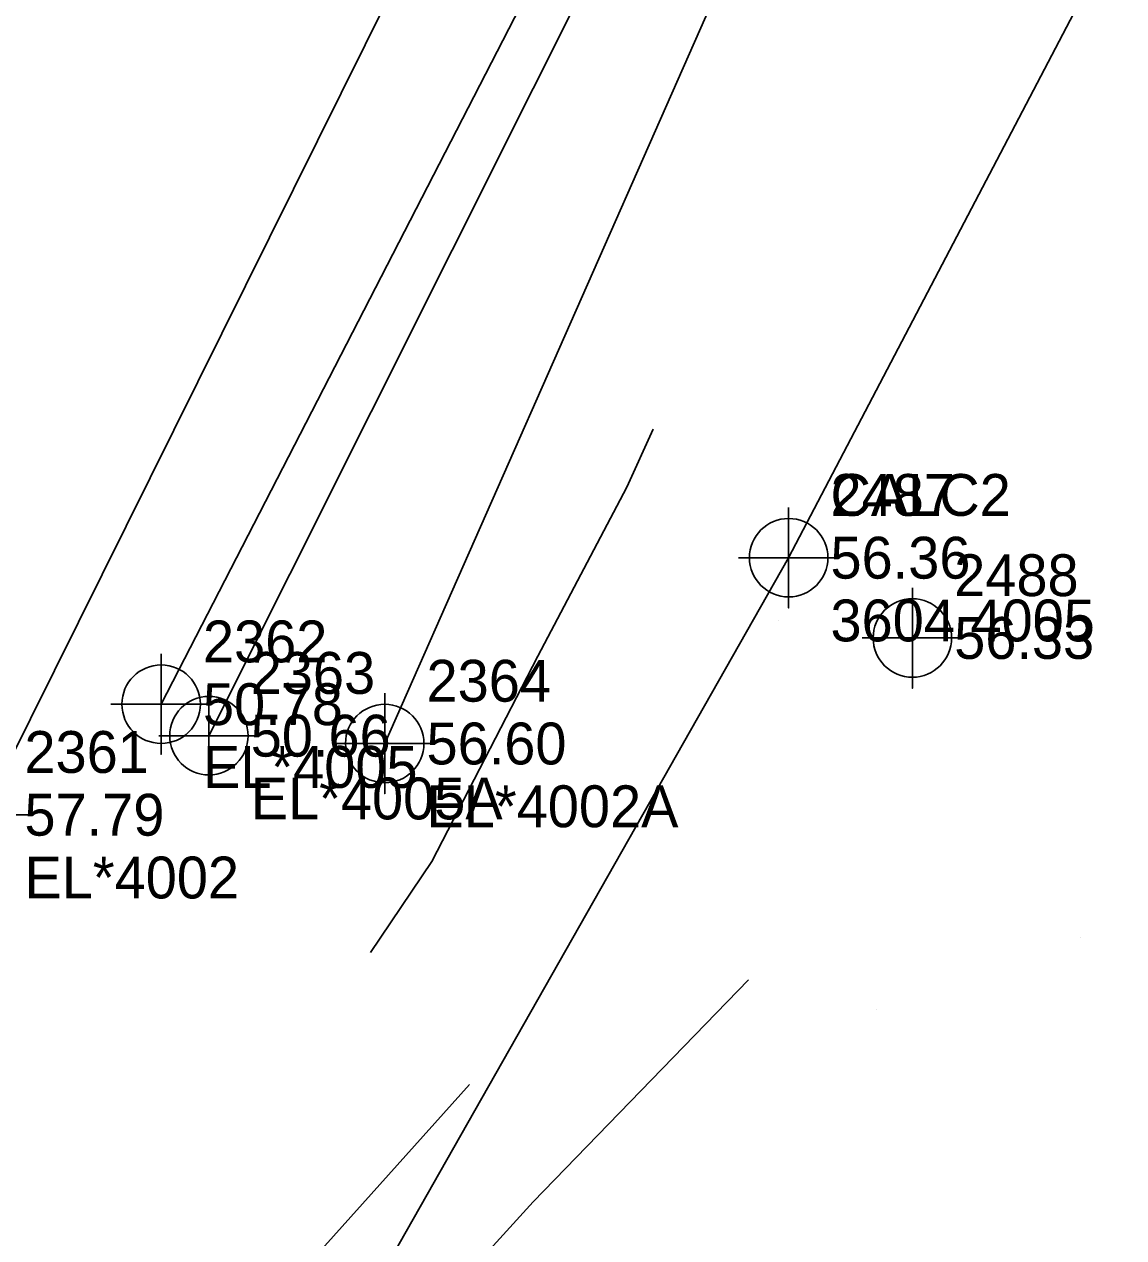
# Model space of a CAD drawing. Extents: x 2062781 to 2066835, y 358981 to 366501.
# Drawn here: x 2065856.5 to 2065922.3, y 364830.6 to 364903.1 of the extents above; entities that cross this region are included whole.
import ezdxf

# ---------------------------------------------------------------- set-up
doc = ezdxf.new("R2010")
doc.units = 0
for name, color, linetype in [('Exist DTM Breakline', 7, 'Continuous'), ('Exist DTM Breakline Cogo Comment', 7, 'Continuous'), ('Exist DTM Breakline Cogo Elevation', 7, 'Continuous'), ('Exist DTM Breakline Cogo Number', 7, 'Continuous'), ('Exist DTM Breakline Cogo Point CELL', 7, 'Continuous'), ('Exist DTM Regular Point CELL', 7, 'Continuous'), ('Exist DTM Regular Point Cogo Elevation', 7, 'Continuous'), ('Exist DTM Regular Point Cogo Number', 7, 'Continuous'), ('Exist DTM Ridgeline', 7, 'Continuous'), ('Exist DTM Ridgeline Cogo Comment', 7, 'Continuous'), ('Exist DTM Ridgeline Cogo Elevation', 7, 'Continuous'), ('Exist DTM Ridgeline Cogo Number', 7, 'Continuous'), ('Exist DTM Ridgeline Cogo Point CELL', 7, 'Continuous'), ('Exist Vegetation Woods Line Cogo Comment', 7, 'Continuous'), ('Exist Vegetation Woods Line Cogo Elevation', 7, 'Continuous'), ('Exist Vegetation Woods Line Cogo Number', 7, 'Continuous'), ('Exist Vegetation Woods Line Cogo Point CELL', 7, 'Continuous'), ('PH Exist DTM Breakline', 7, 'Continuous'), ('PH Exist DTM Point', 7, 'Continuous')]:
    doc.layers.add(name, color=color, linetype=linetype)

msp = doc.modelspace()

# ---------------------------------------------------------------- linework, layer by layer
at = {"layer": 'Exist DTM Breakline'}
for points in [[(2066156.831, 365415.162), (2066147.019, 365417.178), (2066143.489, 365410.654), (2066124.678, 365374.26), (2066094.453, 365314.73), (2066075.651, 365276.959), (2066045.171, 365217.477), (2066024.762, 365178.909), (2065998.134, 365126.307), (2065983.135, 365093.29), (2065946.309, 365022.693), (2065928.627, 364987.732), (2065911.277, 364951.078), (2065894.864, 364921.035), (2065864.729, 364862.524)], [(2065873.933, 364821.446), (2065902.239, 364871.276), (2065926.062, 364916.763), (2065947.617, 364959.443), (2065971.326, 365009.169), (2065993.897, 365049.823), (2066019.053, 365099.44), (2066039.618, 365148.518), (2066072.344, 365204.049), (2066087.274, 365228.935), (2066099.252, 365280.241), (2066129.663, 365320.058), (2066145.915, 365357.967), (2066159.767, 365397.858)], [(2066127.416, 365372.912), (2066101.055, 365319.983), (2066073.267, 365269.359), (2066045.661, 365212.892), (2066026.843, 365177.403), (2066002.142, 365127.603), (2065983.117, 365089.002), (2065947.826, 365021.487), (2065930.43, 364985.775), (2065912.11, 364947.437), (2065896.668, 364918.686), (2065867.585, 364860.642)]]:
    msp.add_lwpolyline(points, dxfattribs=at)
at = {"layer": 'Exist DTM Breakline Cogo Point CELL'}
for points in [[(2065902.239, 364874.276), (2065902.239, 364868.276), (2065902.239, 364871.276), (2065905.239, 364871.276), (2065899.239, 364871.276)], [(2065864.729, 364865.524), (2065864.729, 364859.524), (2065864.729, 364862.524), (2065867.729, 364862.524), (2065861.729, 364862.524)], [(2065867.585, 364863.642), (2065867.585, 364857.642), (2065867.585, 364860.642), (2065870.585, 364860.642), (2065864.585, 364860.642)]]:
    msp.add_lwpolyline(points, dxfattribs=at)
for centre in [(2065902.239, 364871.276), (2065864.729, 364862.524), (2065867.585, 364860.642)]:
    msp.add_circle(centre, 2.344, dxfattribs=at)
at = {"layer": 'Exist DTM Regular Point CELL'}
msp.add_lwpolyline([(2065909.633, 364869.48), (2065909.633, 364863.48), (2065909.633, 364866.48), (2065912.633, 364866.48), (2065906.633, 364866.48)], dxfattribs=at)
msp.add_circle((2065909.633, 364866.48), 2.344, dxfattribs=at)
at = {"layer": 'Exist DTM Ridgeline'}
for points in [[(2066156.481, 365405.544), (2066153.584, 365408.816), (2066148.828, 365401.827), (2066130.845, 365367.475), (2066102.235, 365310.106), (2066082.133, 365275.192), (2066050.596, 365208.968), (2066033.354, 365172.812), (2066001.322, 365110.628), (2065987.751, 365082.522), (2065957.717, 365023.23), (2065937.354, 364979.103), (2065900.972, 364911.969), (2065878.093, 364860.174)], [(2065976.036, 365100.899), (2065942.683, 365025.14), (2065922.614, 364991.082), (2065906.726, 364956.7), (2065890.117, 364964.265), (2065885.103, 364954.915), (2065900.422, 364943.727), (2065889.778, 364927.81), (2065854.059, 364855.919)]]:
    msp.add_lwpolyline(points, dxfattribs=at)
at = {"layer": 'Exist DTM Ridgeline Cogo Point CELL'}
for points in [[(2065878.093, 364863.174), (2065878.093, 364857.174), (2065878.093, 364860.174), (2065881.093, 364860.174), (2065875.093, 364860.174)], [(2065854.059, 364858.919), (2065854.059, 364852.919), (2065854.059, 364855.919), (2065857.059, 364855.919), (2065851.059, 364855.919)]]:
    msp.add_lwpolyline(points, dxfattribs=at)
msp.add_circle((2065878.093, 364860.174), 2.344, dxfattribs=at)
at = {"layer": 'Exist Vegetation Woods Line Cogo Point CELL'}
msp.add_lwpolyline([(2065902.239, 364874.276), (2065902.239, 364868.276), (2065902.239, 364871.276), (2065905.239, 364871.276), (2065899.239, 364871.276)], dxfattribs=at)
msp.add_circle((2065902.239, 364871.276), 2.344, dxfattribs=at)
at = {"layer": 'PH Exist DTM Breakline'}
for points in [[(2065894.142, 364878.961), (2065892.557, 364875.499), (2065887.254, 364865.389), (2065880.915, 364853.132), (2065877.238, 364847.685)], [(2065899.846, 364846.062), (2065886.974, 364832.797), (2065877.811, 364822.715), (2065869.19, 364811.821), (2065858.22, 364793.455), (2065848.645, 364771.182), (2065836.236, 364749.624), (2065826.597, 364727.721), (2065816.132, 364702.31), (2065802.391, 364676.243), (2065787.664, 364653.203), (2065784.063, 364648.086), (2065780.236, 364643.22), (2065773.822, 364636.91), (2065769.303, 364632.582), (2065764.499, 364628.143), (2065758.611, 364624.785), (2065756.783, 364622.952), (2065753.37, 364618.312), (2065750.455, 364614.803), (2065749.265, 364610.283), (2065748.687, 364598.682), (2065747.576, 364591.486)], [(2065873.991, 364829.587), (2065883.161, 364839.799)]]:
    msp.add_lwpolyline(points, dxfattribs=at)
at = {"layer": 'PH Exist DTM Point'}
for p, q in [((2065901.639, 364867.514), (2065901.639, 364867.514)), ((2065919.674, 364848.579), (2065919.674, 364848.579)), ((2065907.517, 364844.275), (2065907.517, 364844.275))]:
    msp.add_line(p, q, dxfattribs=at)

# ---------------------------------------------------------------- texts
at = {"layer": 'Exist DTM Breakline Cogo Comment'}
for s, p in [('EL*4005', (2065867.229, 364857.524)), ('EL*4005A', (2065870.085, 364855.642))]:
    msp.add_text(s, height=2.5, dxfattribs=at).set_placement(p)
at = {"layer": 'Exist DTM Breakline Cogo Elevation'}
for s, p in [('56.36', (2065904.739, 364870.026)), ('50.78', (2065867.229, 364861.274)), ('50.66', (2065870.085, 364859.392))]:
    msp.add_text(s, height=2.5, dxfattribs=at).set_placement(p)
at = {"layer": 'Exist DTM Breakline Cogo Number'}
for s, p in [('CALC2', (2065904.739, 364873.776)), ('2362', (2065867.229, 364865.024)), ('2363', (2065870.085, 364863.142))]:
    msp.add_text(s, height=2.5, dxfattribs=at).set_placement(p)
at = {"layer": 'Exist DTM Regular Point Cogo Elevation'}
msp.add_text('56.33', height=2.5, dxfattribs=at).set_placement((2065912.133, 364865.23))
at = {"layer": 'Exist DTM Regular Point Cogo Number'}
msp.add_text('2488', height=2.5, dxfattribs=at).set_placement((2065912.133, 364868.98))
at = {"layer": 'Exist DTM Ridgeline Cogo Comment'}
for s, p in [('EL*4002A', (2065880.593, 364855.174)), ('EL*4002', (2065856.559, 364850.919))]:
    msp.add_text(s, height=2.5, dxfattribs=at).set_placement(p)
at = {"layer": 'Exist DTM Ridgeline Cogo Elevation'}
for s, p in [('56.60', (2065880.593, 364858.924)), ('57.79', (2065856.559, 364854.669))]:
    msp.add_text(s, height=2.5, dxfattribs=at).set_placement(p)
at = {"layer": 'Exist DTM Ridgeline Cogo Number'}
for s, p in [('2364', (2065880.593, 364862.674)), ('2361', (2065856.559, 364858.419))]:
    msp.add_text(s, height=2.5, dxfattribs=at).set_placement(p)
at = {"layer": 'Exist Vegetation Woods Line Cogo Comment'}
msp.add_text('3604 4005', height=2.5, dxfattribs=at).set_placement((2065904.739, 364866.276))
at = {"layer": 'Exist Vegetation Woods Line Cogo Elevation'}
msp.add_text('56.36', height=2.5, dxfattribs=at).set_placement((2065904.739, 364870.026))
at = {"layer": 'Exist Vegetation Woods Line Cogo Number'}
msp.add_text('2487', height=2.5, dxfattribs=at).set_placement((2065904.739, 364873.776))

doc.saveas('drawing.dxf')
